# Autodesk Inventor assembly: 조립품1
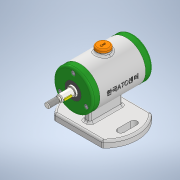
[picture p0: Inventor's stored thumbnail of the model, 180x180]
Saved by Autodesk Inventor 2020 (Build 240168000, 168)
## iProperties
Created: 2021-09
Part Number: 조립품1
Document SubType Name: Assembly
Designer: Administrator
Author: Administrator
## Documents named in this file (10)
- C:\Users\Administrator\Desktop\710906V1013\조립품1.iam
- C:\Users\Administrator\Desktop\710906V1013\본체.ipt
- C:\Users\Administrator\Desktop\710906V1013\베어링 15x32x9.ipt
- C:\Users\Administrator\Desktop\710906V1013\앞커버.ipt
- C:\Users\Administrator\Desktop\710906V1013\뒤커버.ipt
- C:\Users\Administrator\Desktop\710906V1013\캡.ipt
- C:\Users\Administrator\Desktop\710906V1013\오일 실 15x25x7.ipt
- C:\Users\Administrator\Desktop\710906V1013\볼트 M4x12.ipt
- C:\Users\Administrator\Desktop\710906V1013\축.ipt
- C:\Users\Administrator\Desktop\710906V1013\키 3x3.ipt
